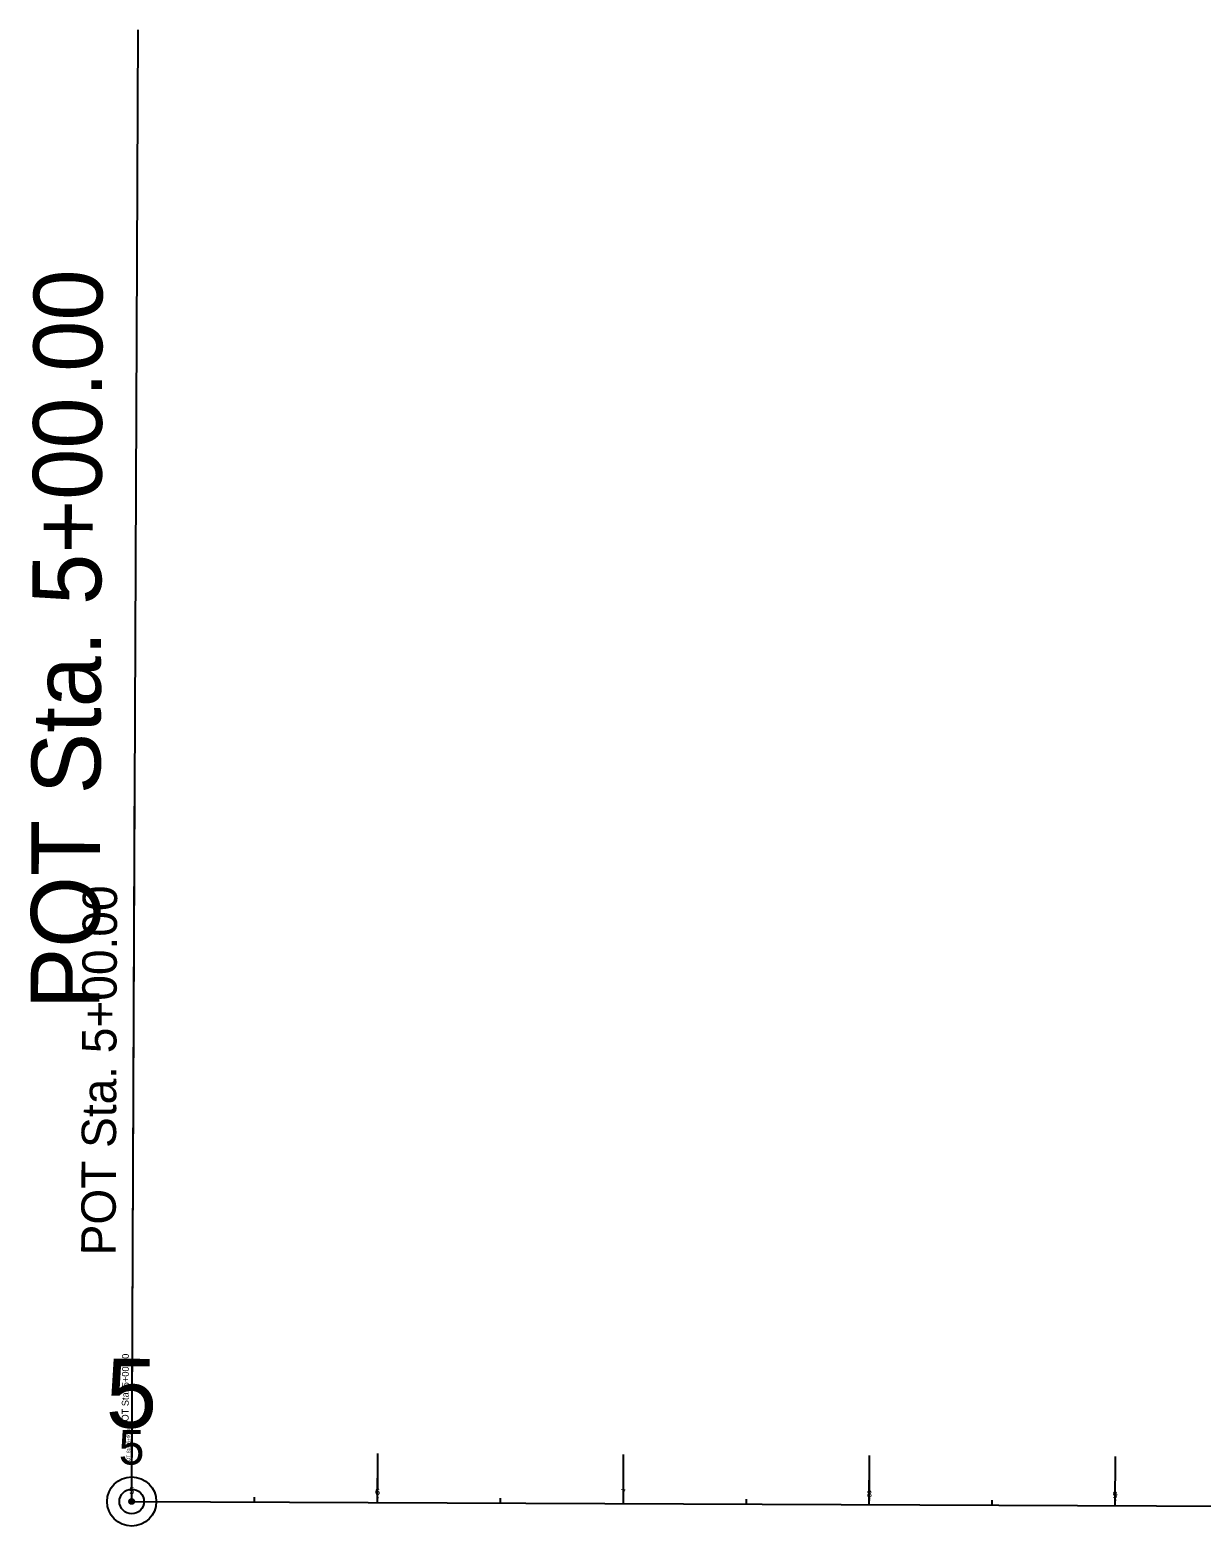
# Model space of a CAD drawing. Extents: x 1794716 to 1797874, y 325521 to 329174.
# Drawn here: x 1794716 to 1795192, y 327521 to 328129 of the extents above; entities that cross this region are included whole.
import ezdxf

# ---------------------------------------------------------------- set-up
doc = ezdxf.new("R2010")
doc.units = 0
for name, color, linetype in [('GE_P_CL_10', 7, 'Continuous'), ('GE_P_CL_100', 7, 'Continuous'), ('GE_P_CL_20', 7, 'Continuous'), ('GE_P_CL_200', 7, 'Continuous'), ('GE_P_CL_25', 7, 'Continuous'), ('GE_X_CL_30', 7, 'Continuous'), ('GK_Visualization', 7, 'Continuous'), ('RW_X_CL_20', 7, 'Continuous')]:
    doc.layers.add(name, color=color, linetype=linetype)

msp = doc.modelspace()

# ---------------------------------------------------------------- linework, layer by layer
at = {"layer": 'GE_P_CL_10'}
for p, q in [((1794757.21, 327531.54), (1794757.36, 327565.95)), ((1794757.21, 327531.04), (1794757.22, 327532.04)), ((1794807.21, 327530.83), (1794807.22, 327531.83)), ((1794857.21, 327530.61), (1794857.22, 327531.61)), ((1794907.21, 327530.39), (1794907.22, 327531.39)), ((1794757.21, 327531.04), (1796269.93, 327524.51)), ((1794957.21, 327530.18), (1794957.22, 327531.18)), ((1795007.21, 327529.96), (1795007.21, 327530.96)), ((1795057.21, 327529.75), (1795057.21, 327530.75)), ((1795107.21, 327529.53), (1795107.21, 327530.53)), ((1795157.21, 327529.31), (1795157.21, 327530.31))]:
    msp.add_line(p, q, dxfattribs=at)
msp.add_circle((1794757.21, 327531.04), 0.5, dxfattribs=at)
at = {"layer": 'GE_P_CL_100'}
for p, q in [((1794757.23, 327536.04), (1794758.5, 327830.15)), ((1794757.21, 327531.04), (1794757.26, 327541.04)), ((1794857.21, 327530.61), (1794857.26, 327540.61)), ((1794957.21, 327530.18), (1794957.25, 327540.18)), ((1795057.21, 327529.75), (1795057.25, 327539.75)), ((1795157.21, 327529.31), (1795157.25, 327539.31)), ((1794757.21, 327531.04), (1796269.93, 327524.51))]:
    msp.add_line(p, q, dxfattribs=at)
msp.add_circle((1794757.21, 327531.04), 5, dxfattribs=at)
at = {"layer": 'GE_P_CL_20'}
for p, q in [((1794757.21, 327531.04), (1794757.22, 327533.04)), ((1794807.21, 327530.83), (1794807.22, 327532.83)), ((1794857.21, 327530.61), (1794857.22, 327532.61)), ((1794907.21, 327530.39), (1794907.22, 327532.39)), ((1794957.21, 327530.18), (1794957.22, 327532.18)), ((1795007.21, 327529.96), (1795007.22, 327531.96)), ((1795057.21, 327529.75), (1795057.22, 327531.75)), ((1795107.21, 327529.53), (1795107.22, 327531.53)), ((1795157.21, 327529.31), (1795157.22, 327531.31)), ((1794757.21, 327531.04), (1796269.93, 327524.51))]:
    msp.add_line(p, q, dxfattribs=at)
at = {"layer": 'GE_P_CL_200'}
for p, q in [((1794757.26, 327541.04), (1794759.8, 328129.26)), ((1794757.21, 327531.04), (1794757.3, 327551.04)), ((1794857.21, 327530.61), (1794857.3, 327550.61)), ((1794957.21, 327530.18), (1794957.3, 327550.18)), ((1795057.21, 327529.75), (1795057.3, 327549.75)), ((1795157.21, 327529.31), (1795157.3, 327549.31)), ((1794757.21, 327531.04), (1796269.93, 327524.51))]:
    msp.add_line(p, q, dxfattribs=at)
msp.add_circle((1794757.21, 327531.04), 10, dxfattribs=at)
at = {"layer": 'GE_P_CL_25'}
msp.add_line((1794757.22, 327532.04), (1794757.51, 327600.86), dxfattribs=at)
msp.add_circle((1794757.21, 327531.04), 1, dxfattribs=at)
at = {"layer": 'GE_X_CL_30'}
msp.add_line((1794757.21, 327531.04), (1796269.93, 327524.51), dxfattribs=at)
at = {"layer": 'GK_Visualization'}
for p, q in [((1794757.15, 327530.98), (1794757.28, 327531.11)), ((1794757.15, 327531.11), (1794757.28, 327530.98))]:
    msp.add_line(p, q, dxfattribs=at)
at = {"layer": 'RW_X_CL_20'}
msp.add_line((1794757.21, 327531.04), (1796269.93, 327524.51), dxfattribs=at)

# ---------------------------------------------------------------- texts
at = {"layer": 'GE_P_CL_10'}
for s, rotation, p in [('POT Sta. 5+00.00', 89.75259, (1794756.58, 327546.05)), ('5', 359.75259, (1794756.68, 327532.54)), ('6', 359.75259, (1794856.68, 327532.11)), ('7', 359.75259, (1794956.65, 327531.68)), ('8', 359.75259, (1795056.71, 327531.25)), ('9', 359.75259, (1795156.69, 327530.82))]:
    msp.add_text(s, height=1.4, rotation=rotation, dxfattribs=at).set_placement(p)
at = {"layer": 'GE_P_CL_100'}
for s, rotation, p in [('POT Sta. 5+00.00', 89.75259, (1794750.64, 327631.07)), ('5', 359.75259, (1794751.93, 327546.07))]:
    msp.add_text(s, height=14, rotation=rotation, dxfattribs=at).set_placement(p)
at = {"layer": 'GE_P_CL_20'}
for s, p in [('5', (1794756.16, 327534.05)), ('6', (1794856.14, 327533.62)), ('7', (1794956.09, 327533.18)), ('8', (1795056.21, 327532.75)), ('9', (1795156.16, 327532.32))]:
    msp.add_text(s, height=2.8, rotation=359.75259, dxfattribs=at).set_placement(p)
at = {"layer": 'GE_P_CL_200'}
for s, rotation, p in [('POT Sta. 5+00.00', 89.75259, (1794744.08, 327731.1)), ('5', 359.75259, (1794746.65, 327561.09))]:
    msp.add_text(s, height=28, rotation=rotation, dxfattribs=at).set_placement(p)
at = {"layer": 'GE_P_CL_25'}
msp.add_text('POT Sta. 5+00.00', height=2.8, rotation=89.75259, dxfattribs=at).set_placement((1794755.94, 327561.05))
at = {"layer": 'GK_Visualization'}
msp.add_text('ROAD500', height=0.14, dxfattribs=at).set_placement((1794756.33, 327531.04))

doc.saveas('drawing.dxf')
